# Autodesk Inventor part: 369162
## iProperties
Created: 2006-08
Part Number: 369162
Material: C45K
Description: Paßfeder
Vendor: Autodesk Inc.
Document SubType Name: Modeling
Standard: DIN 6885
Designer: I.Baliuc
Standards Organization: DIN
Language: de-DE
Size Designation: B 8 x 7 x 15
Categories: <MemberInstance Version="R10.0.0"><Categories><Category DisplayName="Wellenteile" InternalName="7f7aeb1f-a693-4053-b835-cee3144e0d98" Mnemonic="SHFT"><Category
Density: 7.85 g/cm^3
Mass: 6.594 g
Surface Area: 5.62 cm^2
Volume: 0.84 cm^3
Abmessung: B 8 x 7 x 15
Author: T.Messerschmitt
Comments: DIN 6885 - B 8 x 7 x 15
Revision Number: 369162
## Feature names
1. Körper1 [Extrusion]
